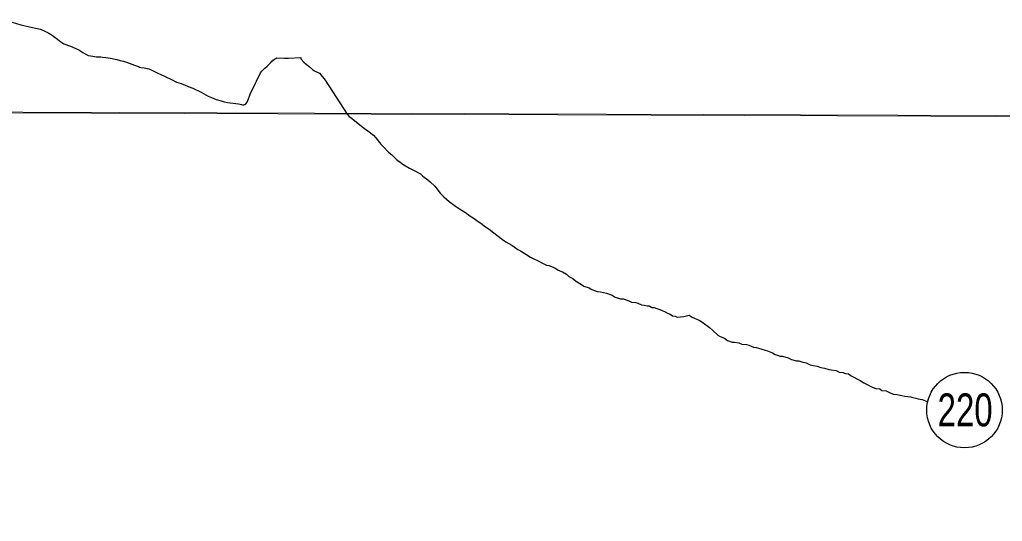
# Model space of a CAD drawing. Extents: x 553962 to 842807, y 8883888 to 9032388.
# Drawn here: x 593467 to 595557, y 8909072 to 8910140 of the extents above; entities that cross this region are included whole.
import ezdxf
from ezdxf.enums import TextEntityAlignment as Align

# ---------------------------------------------------------------- set-up
doc = ezdxf.new("R2010")
doc.units = 0
doc.header["$LTSCALE"] = 200
doc.layers.add('6', color=7, linetype='Continuous', lineweight=13)

msp = doc.modelspace()

# ---------------------------------------------------------------- linework, layer by layer
at = {"layer": '6'}
msp.add_line((574653.9, 8910009.3), (626625.7, 8909822.1), dxfattribs=at)
at = {"layer": '6', "lineweight": 25}
for points in [[(593433.2, 8910140.1), (593470, 8910128.8), (593494.4, 8910123.5), (593501, 8910121.7), (593508.3, 8910120.7), (593511.2, 8910119.9), (593514.7, 8910118.5), (593518.2, 8910117.3), (593522.5, 8910115.2), (593529.6, 8910111), (593532.6, 8910108.9), (593536.4, 8910106.9), (593540, 8910104.1), (593547.8, 8910098.9), (593554.7, 8910093)], [(593554.7, 8910093), (593561.1, 8910088.9), (593575.2, 8910083.7), (593593.1, 8910076.1), (593601.3, 8910070.4), (593606.6, 8910067.2), (593612.7, 8910063.9), (593622.6, 8910062.1), (593626.3, 8910061.8), (593629.6, 8910061.2), (593640, 8910060.7), (593643.5, 8910059.9), (593650.2, 8910059.4), (593660.1, 8910058.2), (593670.6, 8910056), (593673.9, 8910055.6), (593680.7, 8910053.3), (593687.8, 8910051.7), (593694.5, 8910049.6), (593711.2, 8910043.1), (593719.9, 8910040.3), (593721.8, 8910039.2), (593724.7, 8910038.3), (593732, 8910037.7), (593742.2, 8910035.3), (593746.6, 8910033.6), (593761, 8910026.2), (593767.3, 8910023.6), (593775.5, 8910019.8), (593791.3, 8910011.7), (593800.5, 8910007.3), (593810.8, 8910004.2), (593819.1, 8910001), (593825.5, 8909998), (593835.5, 8909994), (593853, 8909985.5), (593867.8, 8909977.5), (593872, 8909976.1), (593875.5, 8909974.1), (593885.1, 8909970.1), (593895.5, 8909967.6), (593902.5, 8909965.3), (593909.1, 8909963.8), (593932.8, 8909961), (593936.4, 8909960), (593939.1, 8909959.7), (593941.1, 8909958.7), (593943.7, 8909958.9), (593946.2, 8909959.5), (593948.1, 8909960.9), (593951.3, 8909964.8), (593954, 8909971.3), (593957.5, 8909981.8), (593969.1, 8910005.1), (593970.9, 8910009.4), (593979.7, 8910026.9), (593982.4, 8910030.4), (593988.7, 8910036.9), (593993.8, 8910041.2), (593996.3, 8910044), (594000.9, 8910048.2), (594004.6, 8910052.2), (594005.8, 8910052.6), (594007.4, 8910054.3), (594010.6, 8910056.6)], [(594010.6, 8910056.6), (594013.9, 8910058.9), (594030.2, 8910058), (594039.3, 8910057.8), (594065.1, 8910059.8)], [(594065.1, 8910059.8), (594065.3, 8910056.9), (594071.5, 8910049.8), (594076.6, 8910045.4), (594082, 8910041.4), (594090.9, 8910033.6), (594094.4, 8910030.9), (594104.6, 8910026.1), (594117, 8910011.3), (594163.5, 8909939)], [(594163.5, 8909939), (594167.3, 8909934.5), (594175.7, 8909928), (594187.2, 8909918.9), (594200.6, 8909908.3), (594207.6, 8909903.2), (594220, 8909894.1), (594224.9, 8909888.6), (594235.3, 8909875), (594240.8, 8909869.4), (594251.7, 8909858.4), (594257.7, 8909853.3), (594268.6, 8909842.7), (594279.1, 8909834.7), (594284, 8909831.1), (594296.5, 8909824), (594304.5, 8909820), (594319.4, 8909811.8), (594324.9, 8909807.3), (594335.3, 8909799.2), (594340.3, 8909795.2), (594350.2, 8909785.6)], [(594350.2, 8909785.6), (594361.6, 8909770.5), (594369.1, 8909762.9), (594381, 8909752.9), (594393.9, 8909742.8), (594402.4, 8909737.7), (594417.8, 8909728.1), (594422.8, 8909724), (594433.7, 8909717), (594439.7, 8909712.9), (594451.2, 8909704.8), (594456.1, 8909700.8), (594465.6, 8909694.2), (594476, 8909686.1), (594482, 8909681.1), (594493.9, 8909672.5), (594500.9, 8909667.4), (594514.3, 8909659.8), (594518.8, 8909656.8), (594526.8, 8909651.2), (594532.2, 8909648.2), (594543.7, 8909641.1), (594553.7, 8909634.6), (594559.6, 8909631.5), (594571.6, 8909625.9), (594576.6, 8909622.9), (594587.5, 8909617.8), (594593, 8909616.8), (594605.5, 8909612.2), (594612.5, 8909607.1), (594622, 8909603.6), (594630.4, 8909598.5), (594635.4, 8909593.4), (594643.8, 8909589.4), (594649.3, 8909584.3), (594661.8, 8909576.2), (594667.2, 8909573.2), (594678.7, 8909569.6), (594684.2, 8909565.6), (594695.7, 8909561.5), (594702.7, 8909561), (594715.6, 8909557.9), (594727.6, 8909553.8), (594733.6, 8909549.7), (594745.1, 8909546.2), (594751.1, 8909546.1), (594763, 8909541.5), (594768.5, 8909538.5), (594777.5, 8909537.9), (594782, 8909536.4), (594790, 8909533.3), (594795.5, 8909532.8), (594801.5, 8909531.3), (594806, 8909530.7), (594811.5, 8909527.7), (594816.5, 8909527.2), (594822.4, 8909525.1), (594828.9, 8909523.1), (594833.9, 8909521), (594840.4, 8909518.5), (594844.9, 8909515.5), (594850.4, 8909513.4), (594855.8, 8909509.4), (594861.3, 8909508.8), (594865.8, 8909506.8), (594879.8, 8909508.2)], [(594879.8, 8909508.2), (594890.9, 8909511.2), (594897.3, 8909507.1), (594913.8, 8909499.5), (594920.8, 8909494.9), (594934.7, 8909484.8), (594940.7, 8909479.3), (594952.1, 8909468.7), (594957.1, 8909465.7), (594966.5, 8909462.1), (594972.5, 8909457.5), (594982.5, 8909454), (594987.5, 8909453.9), (594997, 8909452.4), (595003, 8909449.3), (595013.4, 8909448.8), (595017.9, 8909447.2), (595027.9, 8909443.2), (595033.4, 8909442.6), (595043.4, 8909439.5), (595052.4, 8909436.5), (595057.4, 8909435.4), (595068.3, 8909430.9), (595073.8, 8909427.8), (595084.3, 8909424.2), (595089.3, 8909424.2), (595101.8, 8909420.6), (595108.8, 8909417.1), (595119.7, 8909414), (595124.2, 8909414), (595133.2, 8909410.9), (595140.2, 8909409.4), (595148.2, 8909405.3), (595155.2, 8909404.2), (595163.2, 8909402.7), (595171.2, 8909400.1), (595179.1, 8909398.6), (595188.1, 8909395.5), (595193.1, 8909395), (595203.6, 8909393.4), (595210.1, 8909389.9), (595218.1, 8909388.8), (595223.6, 8909387.3), (595230.1, 8909386.2), (595235.5, 8909382.2), (595241.5, 8909379.2), (595248, 8909375.6), (595255, 8909372.1), (595262.9, 8909367), (595270.9, 8909362.9), (595278.9, 8909358.9), (595287.8, 8909355.3), (595296.3, 8909354.2), (595300.8, 8909350.7), (595310.3, 8909350.2), (595317.3, 8909346.6), (595324.8, 8909343.1), (595332.8, 8909342), (595343.3, 8909340.4), (595349.8, 8909338.9), (595362.2, 8909337.3), (595366.7, 8909335.8), (595373.2, 8909334.7), (595378.2, 8909333.2), (595386.7, 8909331.6), (595397.5, 8909327.7)]]:
    msp.add_lwpolyline(points, dxfattribs=at)
at = {"layer": '6'}
msp.add_lwpolyline([(596575.8, 8909932.4), (585614.8, 8909969.8), (585583.8, 8898914.4), (596544.8, 8898874.9)], close=True, dxfattribs=at)
at = {"layer": '6', "lineweight": 25}
msp.add_circle((595476.7, 8909309.2), 80.3, dxfattribs=at)

# ---------------------------------------------------------------- texts
at = {"layer": '6', "width": 0.75}
msp.add_text('220', height=70, dxfattribs=at).set_placement((595478, 8909274.6), align=Align.CENTER)

doc.saveas('drawing.dxf')
